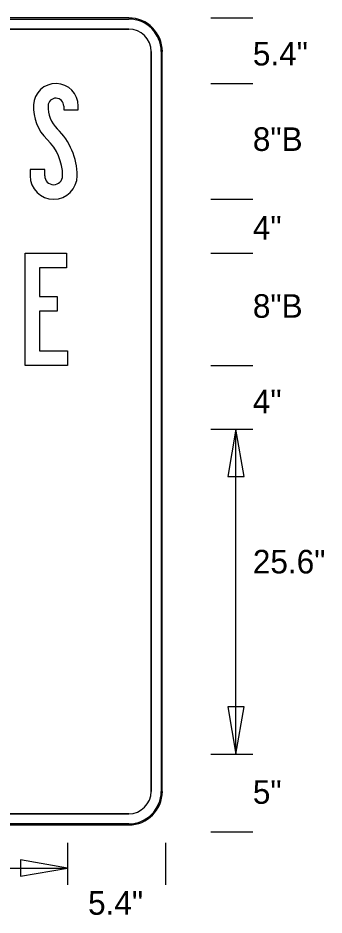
# Model space of a CAD drawing. Extents: x 0 to 770, y 0 to 495.
# Drawn here: x 699.7 to 745.1, y 9.6 to 142.6 of the extents above; entities that cross this region are included whole.
import ezdxf

# ---------------------------------------------------------------- set-up
doc = ezdxf.new("R2010")
doc.units = 0
for name, color, linetype in [('Dimension', 7, 'Continuous'), ('GSBWFill', 7, 'Continuous'), ('GSColorFill', 7, 'Continuous'), ('GSDims', 7, 'Continuous'), ('GSOutline', 7, 'Continuous')]:
    doc.layers.add(name, color=color, linetype=linetype)

msp = doc.modelspace()

# ---------------------------------------------------------------- linework, layer by layer
at = {"layer": 'Dimension'}
for points in [[(732.08, 81.63), (730.89, 74.61), (733.27, 74.61)], [(732.08, 33.43), (733.27, 40.45), (730.89, 40.45)], [(707.1, 16.54), (700.08, 17.73), (700.08, 15.35)]]:
    msp.add_lwpolyline(points, close=True, dxfattribs=at)
at = {"layer": 'GSBWFill'}
for p, q in [((716.16, 142.62), (626.38, 142.62)), ((626.38, 140.96), (716.16, 140.96)), ((719.48, 137.64), (719.48, 27.91)), ((721.14, 27.91), (721.14, 137.64)), ((716.16, 24.59), (626.4, 24.59)), ((626.4, 22.92), (716.16, 22.92))]:
    msp.add_line(p, q, dxfattribs=at)
for points in [[(706.51, 129.56), (706.51, 128.97), (708.68, 128.97), (708.68, 129.56)], [(703.69, 119.22), (703.69, 120.14), (701.53, 120.14), (701.53, 119.22)]]:
    msp.add_lwpolyline(points, dxfattribs=at)
msp.add_lwpolyline([(706.93, 107.71), (706.93, 105.55), (702.94, 105.55), (702.94, 101.31), (705.52, 101.31), (705.52, 99.15), (702.94, 99.15), (702.94, 93.25), (707.1, 93.25), (707.1, 91.09), (700.78, 91.09), (700.78, 107.71)], close=True, dxfattribs=at)
for centre, radius, start, end in [((716.16, 137.64), 4.99, 0, 90), ((716.16, 137.64), 3.33, 0, 90), ((705.35, 129.56), 3.33, 0, 177.3048), ((705.35, 129.56), 1.16, 0, 177.3048), ((708.67, 129.4), 6.65, 177.3048, 226.0638), ((708.67, 129.4), 4.49, 177.3048, 226.0638), ((698.87, 119.22), 9.64, 0, 46.0638), ((698.87, 119.22), 7.48, 0, 46.0638), ((705.02, 119.22), 3.49, 180, 0), ((705.02, 119.22), 1.33, 180, 0), ((716.16, 27.91), 4.99, 270, 0), ((716.16, 27.91), 3.33, 270, 0)]:
    msp.add_arc(centre, radius, start, end, dxfattribs=at)
at = {"layer": 'GSColorFill'}
for p, q in [((716.16, 142.62), (626.38, 142.62)), ((716.16, 142.62), (626.38, 142.62)), ((716.16, 142.62), (626.38, 142.62)), ((626.38, 142.46), (716.16, 142.46)), ((626.38, 140.96), (716.16, 140.96)), ((719.48, 137.64), (719.48, 27.91)), ((720.98, 137.64), (720.98, 27.91)), ((721.14, 27.91), (721.14, 137.64)), ((721.14, 27.91), (721.14, 137.64)), ((721.14, 27.91), (721.14, 137.64)), ((716.16, 24.59), (626.4, 24.59)), ((716.16, 23.09), (626.38, 23.09)), ((626.38, 22.92), (716.16, 22.92)), ((626.38, 22.92), (716.16, 22.92)), ((626.4, 22.92), (716.16, 22.92))]:
    msp.add_line(p, q, dxfattribs=at)
for points in [[(706.51, 129.56), (706.51, 128.97), (708.68, 128.97), (708.68, 129.56)], [(703.69, 119.22), (703.69, 120.14), (701.53, 120.14), (701.53, 119.22)]]:
    msp.add_lwpolyline(points, dxfattribs=at)
msp.add_lwpolyline([(706.93, 107.71), (706.93, 105.55), (702.94, 105.55), (702.94, 101.31), (705.52, 101.31), (705.52, 99.15), (702.94, 99.15), (702.94, 93.25), (707.1, 93.25), (707.1, 91.09), (700.78, 91.09), (700.78, 107.71)], close=True, dxfattribs=at)
for centre, radius, start, end in [((716.16, 137.64), 4.99, 0, 90), ((716.16, 137.64), 4.99, 0, 90), ((716.16, 137.64), 4.99, 0, 90), ((716.16, 137.64), 4.82, 0, 90), ((716.16, 137.64), 3.33, 0, 90), ((705.35, 129.56), 3.33, 0, 177.3048), ((705.35, 129.56), 1.16, 0, 177.3048), ((708.67, 129.4), 6.65, 177.3048, 226.0638), ((708.67, 129.4), 4.49, 177.3048, 226.0638), ((698.87, 119.22), 9.64, 0, 46.0638), ((698.87, 119.22), 7.48, 0, 46.0638), ((705.02, 119.22), 3.49, 180, 0), ((705.02, 119.22), 1.33, 180, 0), ((716.16, 27.91), 4.99, 270, 0), ((716.16, 27.91), 4.99, 270, 0), ((716.16, 27.91), 3.33, 270, 0), ((716.16, 27.91), 4.99, 270, 0), ((716.16, 27.91), 4.82, 270, 0)]:
    msp.add_arc(centre, radius, start, end, dxfattribs=at)
at = {"layer": 'GSDims'}
for p, q in [((728.33, 142.62), (734.58, 142.62)), ((728.33, 132.88), (734.58, 132.88)), ((728.33, 115.73), (734.58, 115.73)), ((728.33, 107.71), (734.58, 107.71)), ((728.33, 107.71), (734.58, 107.71)), ((728.33, 91.09), (734.58, 91.09)), ((728.33, 81.63), (734.58, 81.63)), ((728.33, 81.63), (734.58, 81.63)), ((732.08, 33.43), (732.08, 81.63)), ((728.33, 33.43), (734.58, 33.43)), ((728.33, 33.43), (734.58, 33.43)), ((728.33, 21.89), (734.58, 21.89)), ((707.1, 20.29), (707.1, 14.04)), ((707.1, 20.29), (707.1, 14.04)), ((721.64, 20.29), (721.64, 14.04)), ((633.86, 16.54), (707.1, 16.54))]:
    msp.add_line(p, q, dxfattribs=at)
at = {"layer": 'GSOutline'}
for p, q in [((716.16, 142.62), (626.38, 142.62)), ((716.16, 140.96), (626.38, 140.96)), ((719.48, 27.91), (719.48, 137.64)), ((721.14, 27.91), (721.14, 137.64)), ((626.38, 24.59), (716.16, 24.59)), ((626.38, 22.92), (716.16, 22.92))]:
    msp.add_line(p, q, dxfattribs=at)
for points in [[(706.51, 129.56), (706.51, 128.97), (708.68, 128.97), (708.68, 129.56)], [(703.69, 119.22), (703.69, 120.14), (701.53, 120.14), (701.53, 119.22)]]:
    msp.add_lwpolyline(points, dxfattribs=at)
msp.add_lwpolyline([(706.93, 107.71), (706.93, 105.55), (702.94, 105.55), (702.94, 101.31), (705.52, 101.31), (705.52, 99.15), (702.94, 99.15), (702.94, 93.25), (707.1, 93.25), (707.1, 91.09), (700.78, 91.09), (700.78, 107.71)], close=True, dxfattribs=at)
for centre, radius, start, end in [((716.16, 137.64), 4.99, 0, 90), ((716.16, 137.64), 3.33, 0, 90), ((705.35, 129.56), 3.33, 0, 177.3048), ((705.35, 129.56), 1.16, 0, 177.3048), ((708.67, 129.4), 6.65, 177.3048, 226.0638), ((708.67, 129.4), 4.49, 177.3048, 226.0638), ((698.87, 119.22), 9.64, 0, 46.0638), ((698.87, 119.22), 7.48, 0, 46.0638), ((705.02, 119.22), 3.49, 180, 0), ((705.02, 119.22), 1.33, 180, 0), ((716.16, 27.91), 4.99, 270, 0), ((716.16, 27.91), 3.33, 270, 0)]:
    msp.add_arc(centre, radius, start, end, dxfattribs=at)

# ---------------------------------------------------------------- texts
at = {"layer": 'GSDims'}
for s, p in [('5.4"', (734.58, 135.57)), ('8"B', (734.58, 122.9)), ('4"', (734.58, 109.76)), ('8"B', (734.58, 98.15)), ('4"', (734.58, 84)), ('25.6"', (734.58, 60.23)), ('5"', (734.58, 26.06)), ('5.4"', (710.13, 9.61))]:
    msp.add_text(s, height=3.5, dxfattribs=at).set_placement(p)

doc.saveas('drawing.dxf')
